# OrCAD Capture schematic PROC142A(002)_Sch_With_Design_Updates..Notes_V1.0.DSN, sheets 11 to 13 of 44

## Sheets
11 10. PERIPHERAL POWER SUPPLY-1: size C; title: PERIPHERAL POWER SUPPLY -1
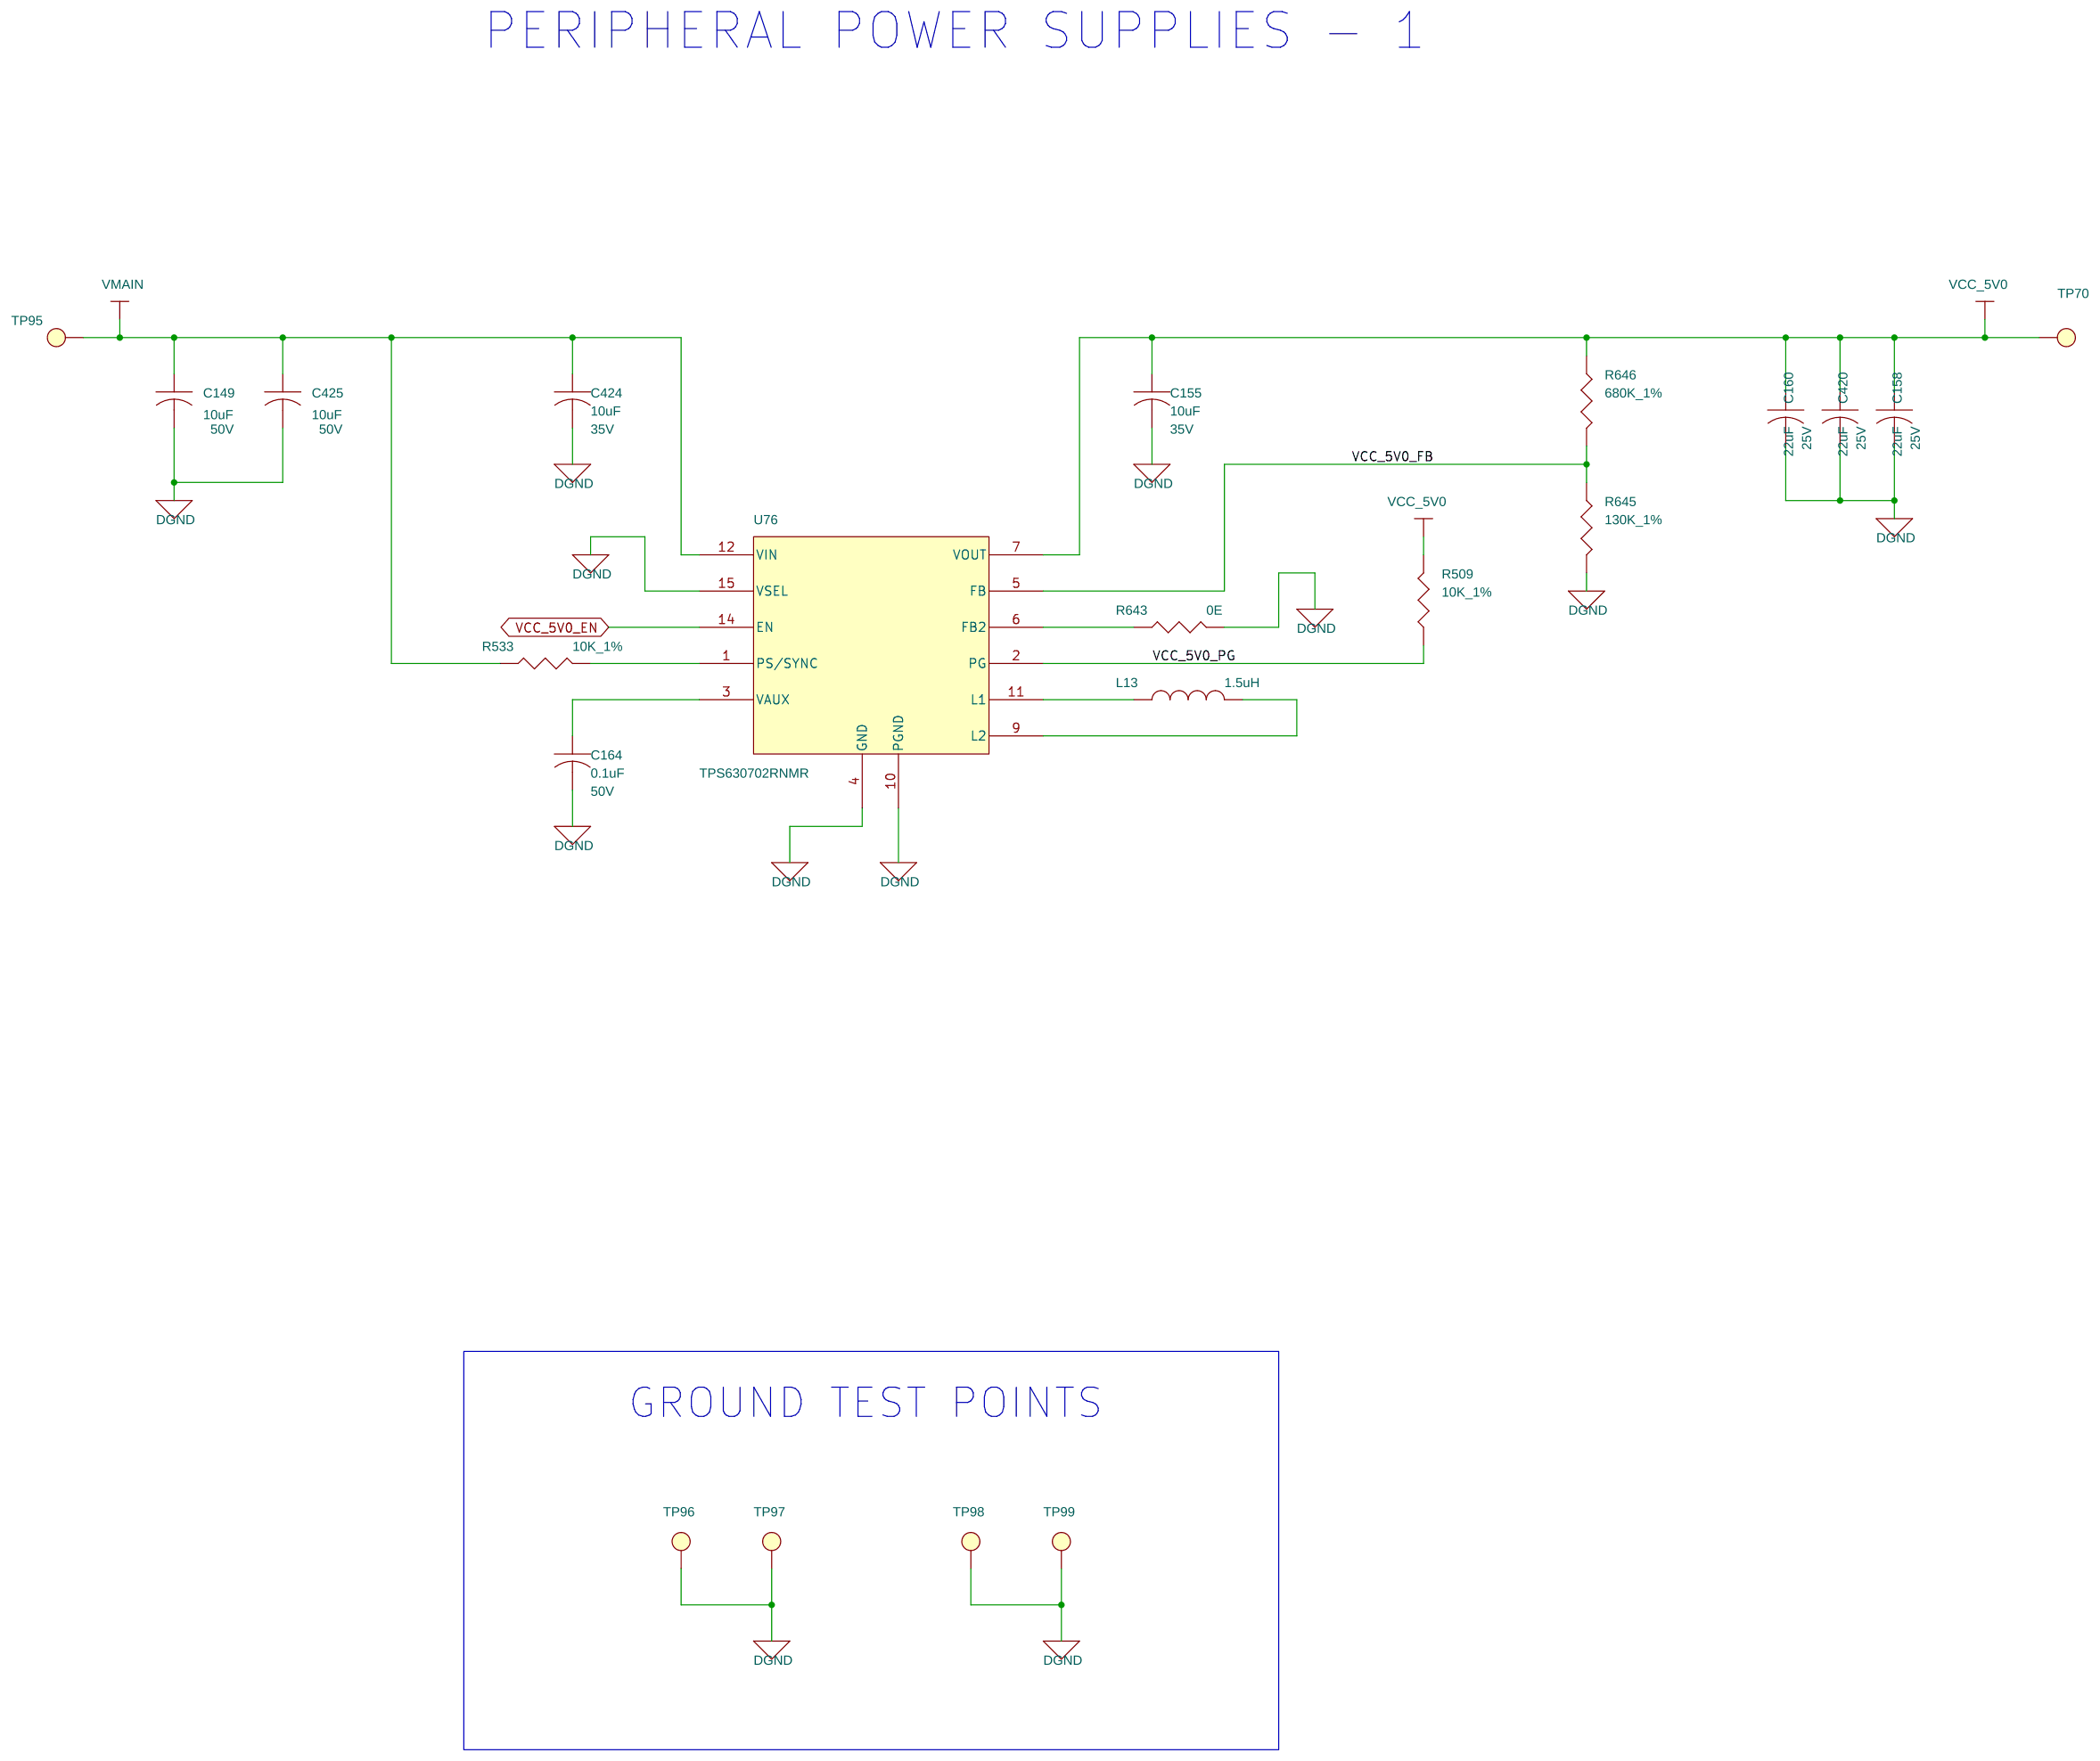
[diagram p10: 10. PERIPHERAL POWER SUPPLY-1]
12 11. PERIPHERAL POWER SUPPLY-2: size C; title: PERIPHERAL POWER SUPPLY-2
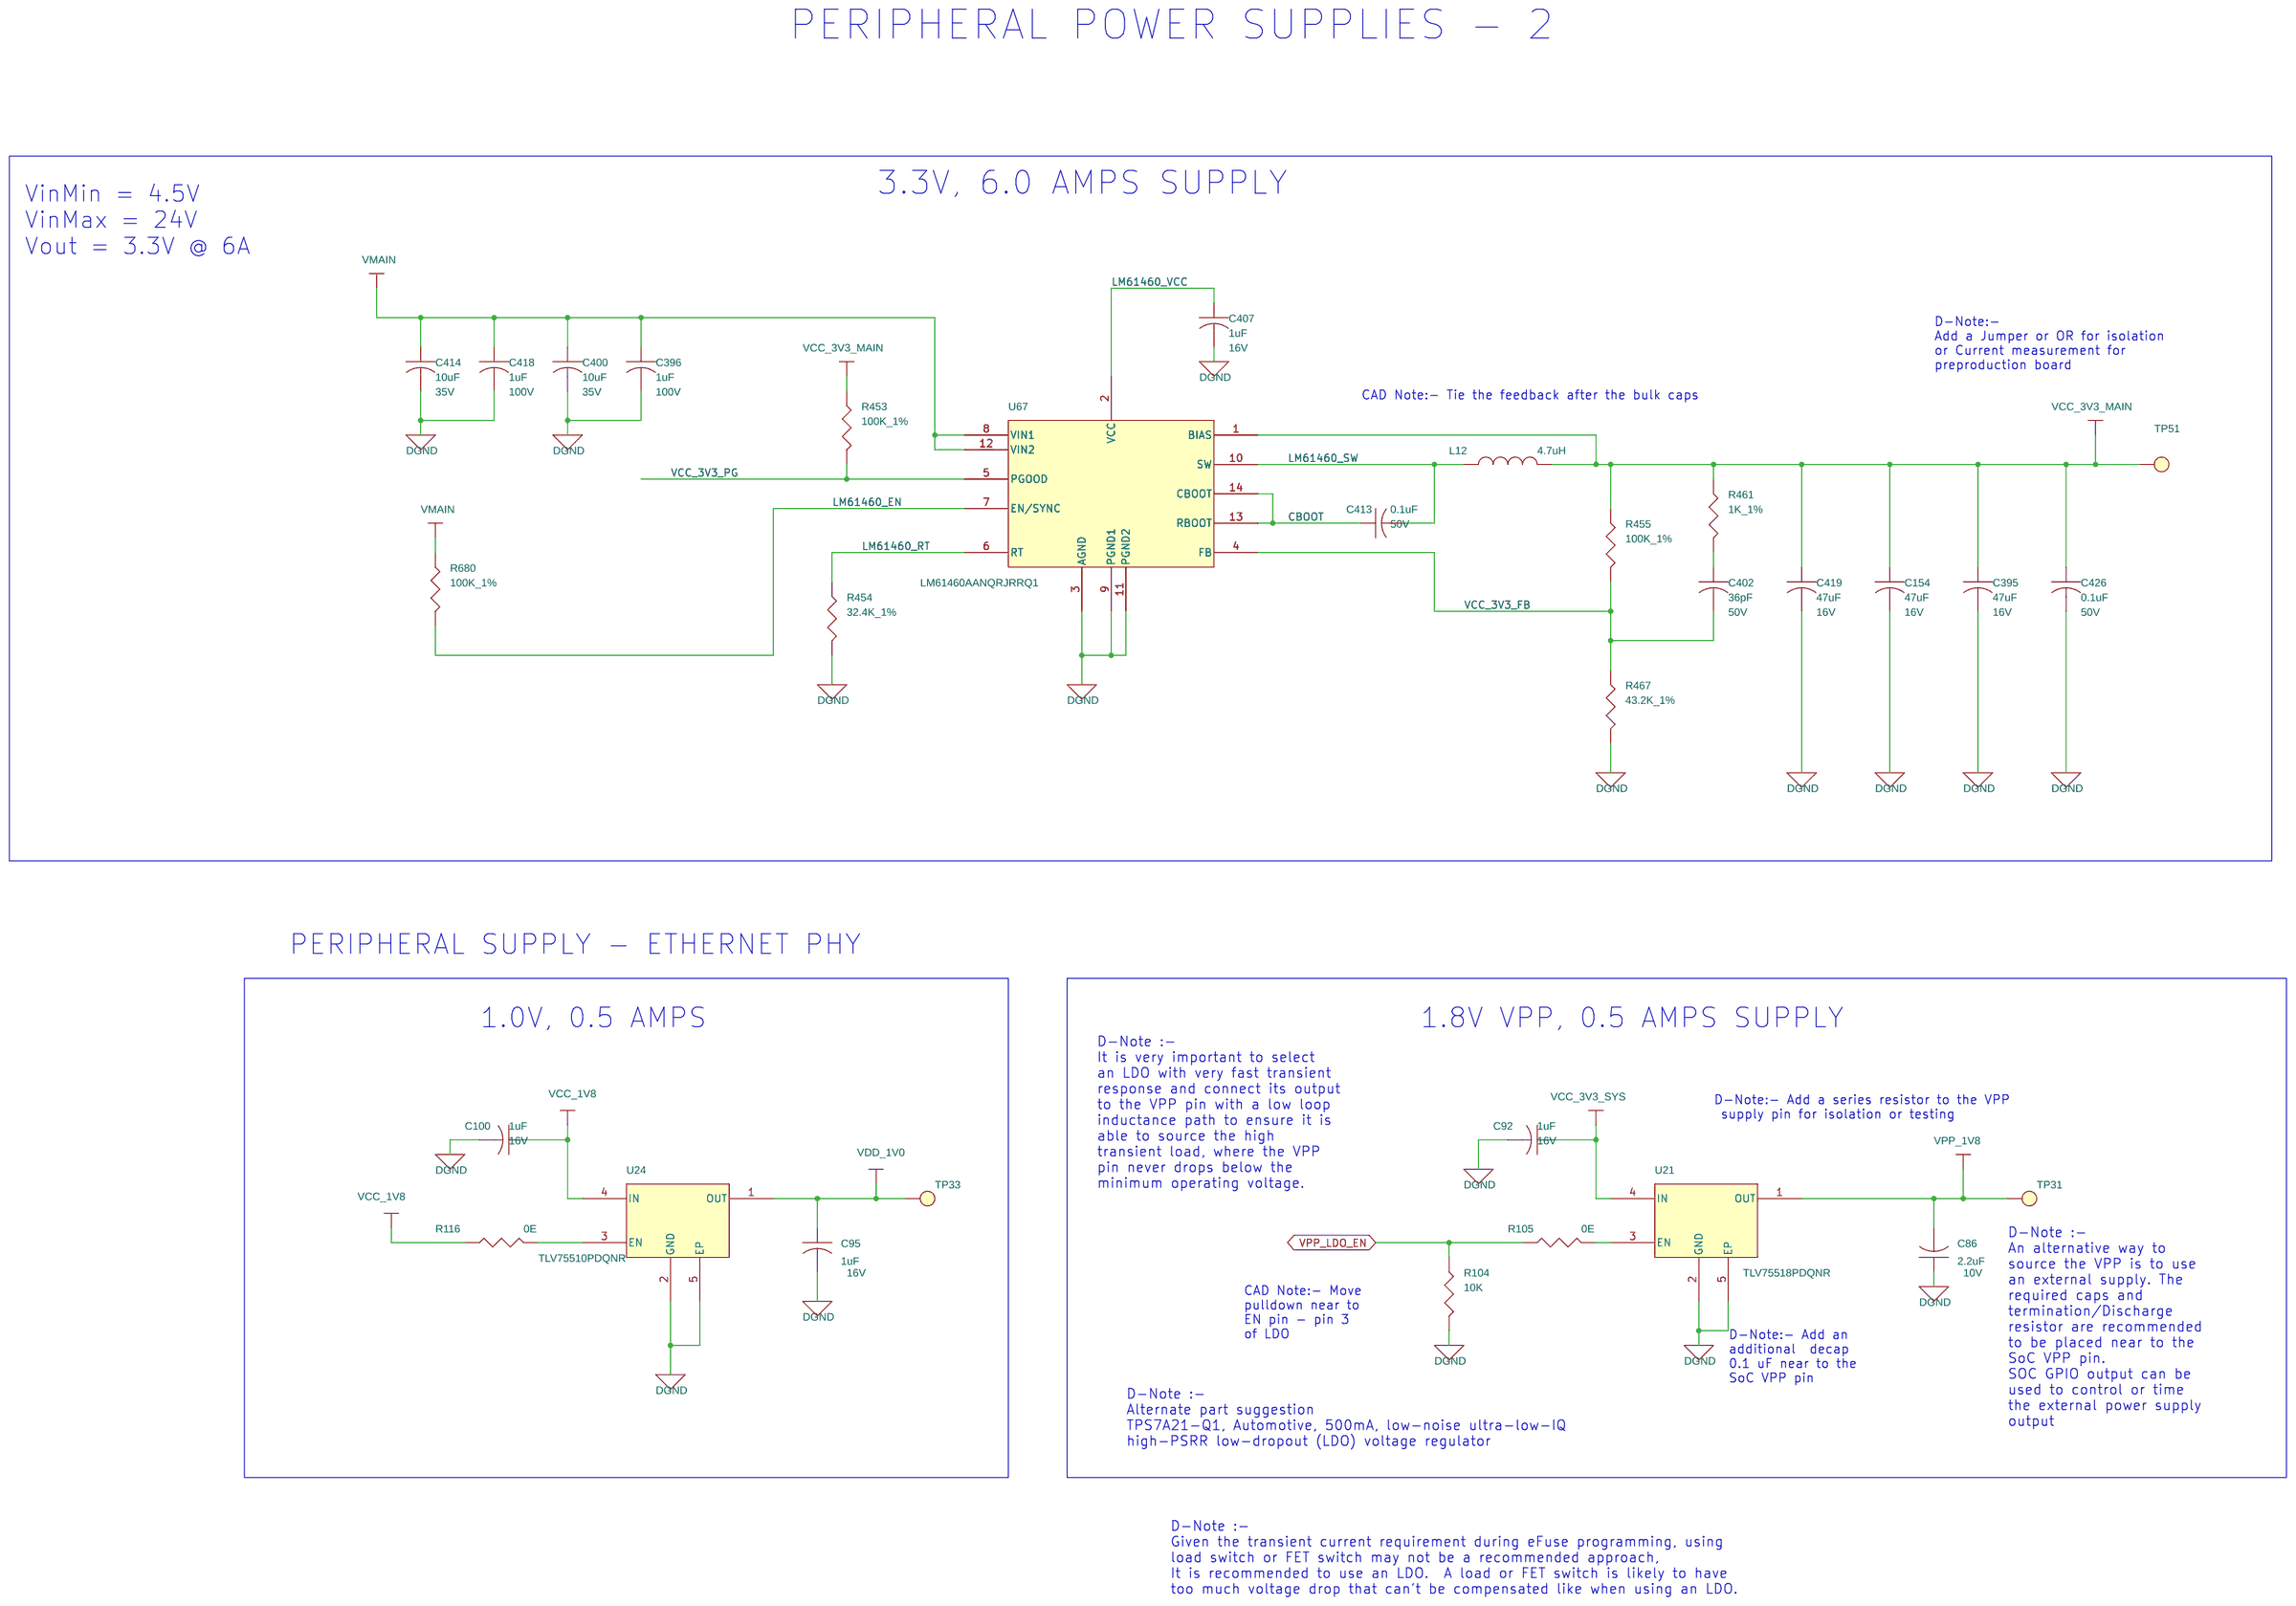
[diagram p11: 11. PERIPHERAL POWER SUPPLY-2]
13 12. FULTON PMIC: size C; title: SOC POWER SUPPLY
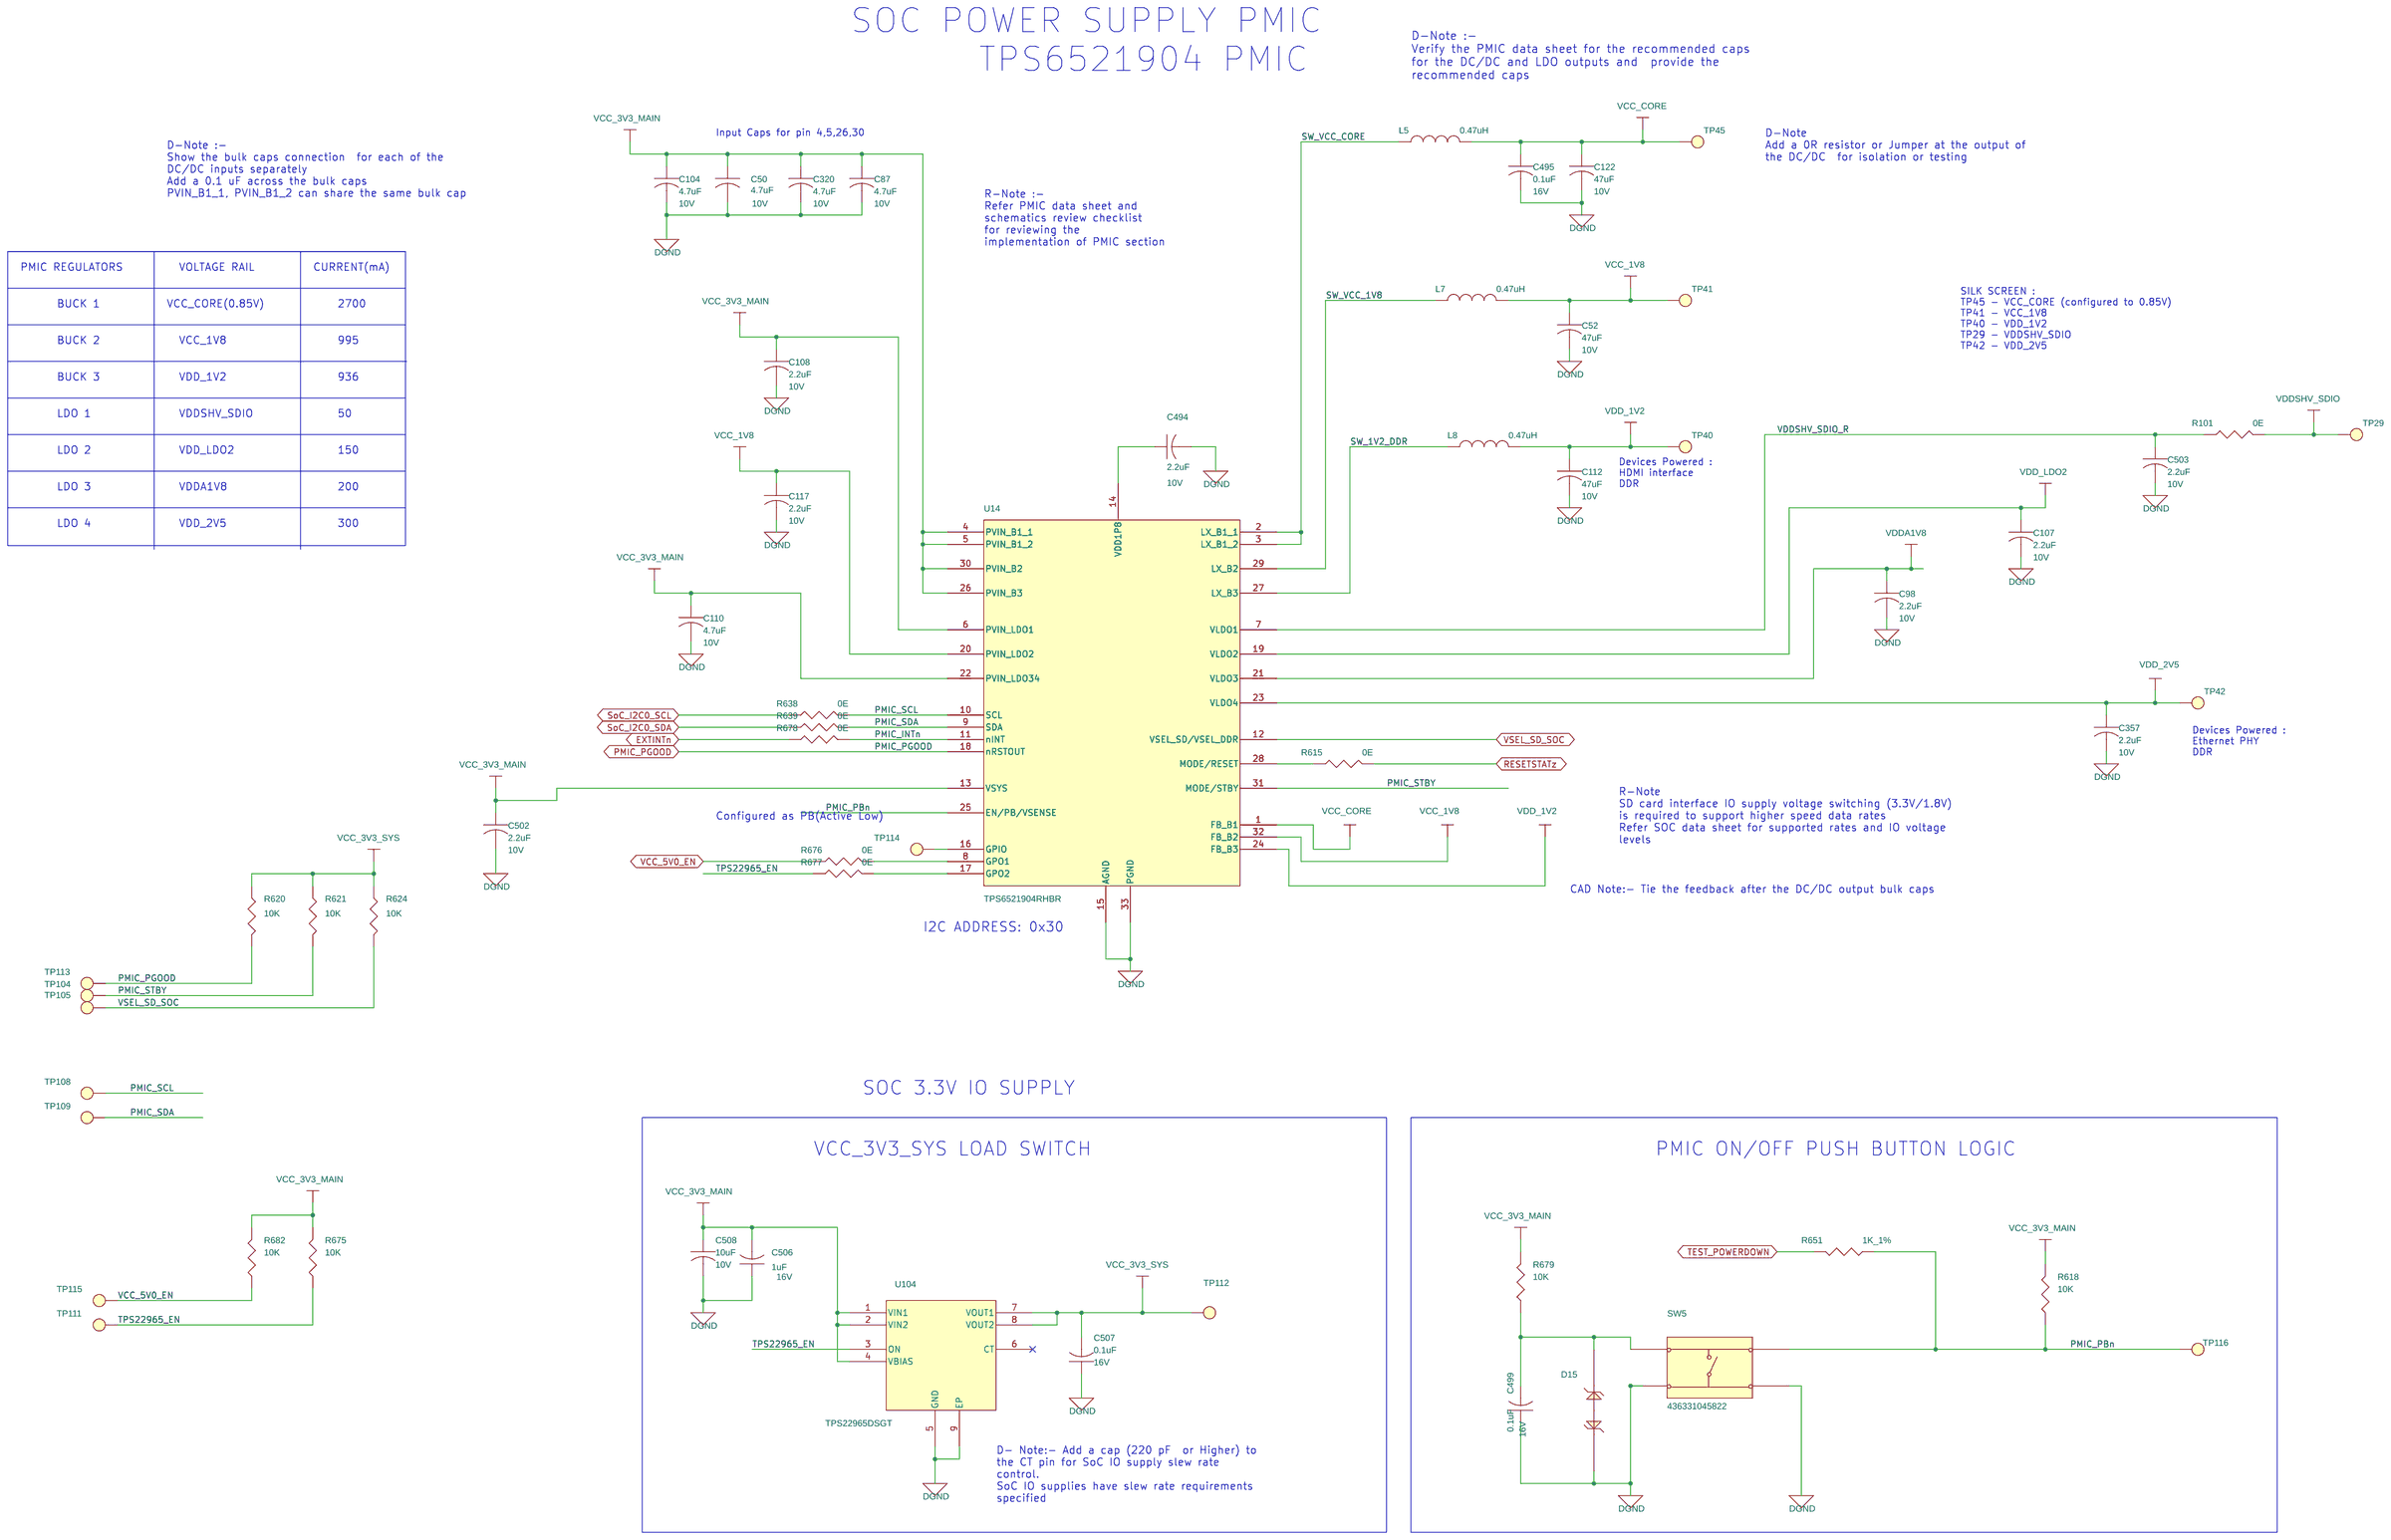
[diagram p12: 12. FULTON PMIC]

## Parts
sheet 10. PERIPHERAL POWER SUPPLY-1
C149  10uF  [CAP0805_1-5]
C155  10uF  [CAP0603_1]
C158  22uF  [CAP0805_1-5]
C160  22uF  [CAP0805_1-5]
C164  0.1uF  [CAP0402_0-75]
C420  22uF  [CAP0805_1-5]
C424  10uF  [CAP0603_1]
C425  10uF  [CAP0805_1-5]
L13  1.5uH  [IND_XFL4020_170X170_SMD_2-1]
R509  10K_1%  [RES0201_0-5]
R533  10K_1%  [RES0201_0-5]
R643  0E  [RES0201_0-5]
R645  130K_1%  [RES0402_0-5]
R646  680K_1%  [RES0402_0-5]
TP70  TP20_SMD  [TP20_SMD]
TP95  TP20_SMD  [TP20_SMD]
TP96  THRU HOLE  [TP_36X22]
TP97  THRU HOLE  [TP_36X22]
TP98  TP20_SMD  [TP20_SMD]
TP99  TP20_SMD  [TP20_SMD]
U76  TPS630702RNMR  [VQFNHR15_TPS630701_100X120_1]
sheet 11. PERIPHERAL POWER SUPPLY-2
C86  2.2uF  [CAP0201_0-5]
C92  1uF  [CAP0201_0-5]
C95  1uF  [CAP0201_0-5]
C100  1uF  [CAP0201_0-5]
C154  47uF  [CAP1210_2-75]
C395  47uF  [CAP1210_2-75]
C396  1uF  [CAP0805_1-5]
C400  10uF  [CAP0603_1]
C402  36pF  [CAP0402_0-75]
C407  1uF  [CAP0201_0-5]
C413  0.1uF  [CAP0402_0-75]
C414  10uF  [CAP0603_1]
C418  1uF  [CAP0805_1-5]
C419  47uF  [CAP1210_2-75]
C426  0.1uF  [CAP0402_0-75]
L12  4.7uH  [IND_XAL6060_260X270_SMD_6-1]
R104  10K  [RES0201_0-5]
R105  0E  [RES0201_0-5]
R116  0E  [RES0201_0-5]
R453  100K_1%  [RES0402_0-5]
R454  32.4K_1%  [RES0402_0-5]
R455  100K_1%  [RES0402_0-5]
R461  1K_1%  [RES0402_0-5]
R467  43.2K_1%  [RES0402_0-5]
R680  100K_1%  [RES0402_0-5]
TP31  TP20_SMD  [TP20_SMD]
TP33  TP20_SMD  [TP20_SMD]
TP51  TP20_SMD  [TP20_SMD]
U21  TLV75518PDQNR  [X2SON4_TLV71318P_40X40_0-4]
U24  TLV75510PDQNR  [X2SON4_TLV71318P_40X40_0-4]
U67  LM61460AANQRJRRQ1  [VQFNHR14_LM61460_160X140_1]
sheet 12. FULTON PMIC
C50  4.7uF  [CAP0402_0-75]
C52  47uF  [CAP0805_1-5]
C87  4.7uF  [CAP0402_0-75]
C98  2.2uF  [CAP0201_0-5]
C104  4.7uF  [CAP0402_0-75]
C107  2.2uF  [CAP0201_0-5]
C108  2.2uF  [CAP0201_0-5]
C110  4.7uF  [CAP0402_0-75]
C112  47uF  [CAP0805_1-5]
C117  2.2uF  [CAP0201_0-5]
C122  47uF  [CAP0805_1-5]
C320  4.7uF  [CAP0402_0-75]
C357  2.2uF  [CAP0201_0-5]
C494  2.2uF  [CAP0201_0-5]
C495  0.1uF  [CAP0201_0-5]
C499  0.1uF  [CAP0201_0-5]
C502  2.2uF  [CAP0201_0-5]
C503  2.2uF  [CAP0201_0-5]
C506  1uF  [CAP0201_0-5]
C507  0.1uF  [CAP0201_0-5]
C508  10uF  [CAP0402_0-75]
D15  TPD1E10B06DPYR  [DIO_DFN0402_0-5]
L5  0.47uH  [IND0806_1-2]
L7  0.47uH  [IND0806_1-2]
L8  0.47uH  [IND0806_1-2]
R101  0E  [RES0402_0-5]
R615  0E  [RES0402_0-5]
R618  10K  [RES0201_0-5]
R620  10K  [RES0201_0-5]
R621  10K  [RES0201_0-5]
R624  10K  [RES0201_0-5]
R638  0E  [RES0201_0-5]
R639  0E  [RES0201_0-5]
R651  1K_1%  [RES0201_0-5]
R675  10K  [RES0201_0-5]
R676  0E  [RES0201_0-5]
R677  0E  [RES0201_0-5]
R678  0E  [RES0201_0-5]
R679  10K  [RES0201_0-5]
R682  10K  [RES0201_0-5]
SW5  436331045822  [SW4_436331045822_190X190_SMD_1-7]
TP29  TP20_SMD  [TP20_SMD]
TP40  TP20_SMD  [TP20_SMD]
TP41  TP20_SMD  [TP20_SMD]
TP42  TP20_SMD  [TP20_SMD]
TP45  TP20_SMD  [TP20_SMD]
TP104  TP20_SMD  [TP20_SMD]
TP105  TP20_SMD  [TP20_SMD]
TP108  TP20_SMD  [TP20_SMD]
TP109  TP20_SMD  [TP20_SMD]
TP111  TP20_SMD  [TP20_SMD]
TP112  TP20_SMD  [TP20_SMD]
TP113  TP20_SMD  [TP20_SMD]
TP114  TP20_SMD  [TP20_SMD]
TP115  TP20_SMD  [TP20_SMD]
TP116  TP20_SMD  [TP20_SMD]
U14  TPS6521904RHBR  [QFN32_19-68_200X200_1_EP3-8]
U104  TPS22965DSGT  [WSON8_19-68_80X80_0-8]

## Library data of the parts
C149 C425 = CAP: CAP CERAMIC 10uF 50V 10% X5R 0805; Chkd/date: MANIRAJA/010321; Crtd /date: ALVY/010321; Custom_Duty: 15%; Customs_HS_Code: 85322990; Distributor_name: DIGIKEY; Distributor_part_number: 490-18663-1-ND; Footprint Path: Y:\MIS_DATABASE\Library\ALTIUM_TOOL\PCB_FOOTPRINTS\Altium_Footprint_Lib.PcbLib; Height: 1.45MM; Library Path: Y:\MIS_DATABASE\Library\ALTIUM_TOOL\SCHEMATICS_PARTS\MS_DISCRETE_Library.schlib; Mfr_name: MURATA; Mfr_part_number: GRM21BR61H106KE43L; Mistral Part No: 120021030002-R; Package: 0805; Part_type: CAPACITORS\CERAMIC; Project: J7ES_SK_BRD; RoHS: RoHS; Temperature: -55°C+85°C; Tolerance: 10%; Voltage: 50V; Wattage: NA; Weight: 6.4mg; Datasheet: Y:\MIS_DATABASE\DATASHEETS\CAPACITORS\GRM21BR61H106KE43.PDF
C155 C400 C414 C424 = CAP: CAP CERAMIC 10uF 35V 20% X5R 0603; Chkd/date: MANIRAJA/170519; Crtd /date: ALVY/160519; Custom_Duty: 15%; Customs_HS_Code: 85322990; Distributor_name: DIGIKEY; Distributor_part_number: 490-13248-1-ND; Footprint Path: Y:\MIS_DATABASE\Library\ALTIUM_TOOL\PCB_FOOTPRINTS\Altium_Footprint_Lib.PcbLib; Height: 1.00MM; Library Path: Y:\MIS_DATABASE\Library\ALTIUM_TOOL\SCHEMATICS_PARTS\MS_DISCRETE_Library.schlib; Mfr_name: MURATA; Mfr_part_number: GRM188R6YA106MA73D; Mistral Part No: 120019050016-R; Package: 0603; Part_type: CAPACITORS\CERAMIC; Project: BRUKER_SD820_COMMONDO; RoHS: RoHS; Temperature: -55°C+85°C; Tolerance: 20%; Voltage: 35V; Wattage: NA; Weight: 9mg; Datasheet: Y:\MIS_DATABASE\DATASHEETS\CAPACITORS\GRM188R6YA106MA73.PDF
C158 C160 C420 = CAP: CAP CERAMIC 22uF 25V 20% X5R 0805; Chkd/date: MANIRAJA/110718; Crtd /date: ALVY/110718; Custom_Duty: 15%; Customs_HS_Code: 85322990; Distributor_name: DIGIKEY; Distributor_part_number: 490-14661-1-ND; Footprint Path: Y:\MIS_DATABASE\Library\ALTIUM_TOOL\PCB_FOOTPRINTS\Altium_Footprint_Lib.PcbLib; Height: 1.45MM; Library Path: Y:\MIS_DATABASE\Library\ALTIUM_TOOL\SCHEMATICS_PARTS\MS_DISCRETE_Library.schlib; Mfr_name: MURATA; Mfr_part_number: GRM21BR61E226ME44K; Mistral Part No: 120013120018-R; Package: 0805; Part_type: CAPACITORS\CERAMIC; Project: TI_J7SVB_PCIE_ADD-ON-CARD; RoHS: RoHS; Temperature: -55°C+85°C; Tolerance: 20%; Voltage: 25V; Wattage: NA; Weight: 9.5mg; Datasheet: Y:\MIS_DATABASE\DATASHEETS\CAPACITORS\GRM21BR61E226ME44K.PDF
C164 C413 C426 = CAP: CAP CERAMIC 0.1uF 50V 10% X7R 0402; Chkd/date: MANIRAJA/261020; Crtd /date: ALVY/211020; Custom_Duty: 15%; Customs_HS_Code: 85322990; Distributor_name: DIGIKEY; Distributor_part_number: 490-10700-1-ND; Footprint Path: Y:\MIS_DATABASE\Library\ALTIUM_TOOL\PCB_FOOTPRINTS\Altium_Footprint_Lib.PcbLib; Height: 0.55MM; Library Path: Y:\MIS_DATABASE\Library\ALTIUM_TOOL\SCHEMATICS_PARTS\MS_DISCRETE_Library.schlib; Mfr_name: MURATA; Mfr_part_number: GRM155R71H104KE14D; Mistral Part No: 120011100014-R; Package: 0402; Part_type: CAPACITORS\CERAMIC; Project: J7_CP; RoHS: RoHS; Temperature: -55°C+125°C; Tolerance: 10%; Voltage: 50V; Wattage: NA; Weight: 3.1mg; Datasheet: Y:\MIS_DATABASE\DATASHEETS\CAPACITORS\GRM155R71H104KE14.PDF
L13 = INDUCTOR: IND POWER 1.5uH 9.1A 20% SMD; Chkd/date: MANIRAJA/101019; Crtd /date: MANIRAJA/101019; Custom_Duty: 24%; Customs_HS_Code: 85437099; Distributor_name: MOUSER; Distributor_part_number: 994-XFL4020-152MEB; Footprint Path: Y:\MIS_DATABASE\Library\ALTIUM_TOOL\PCB_FOOTPRINTS\Altium_Footprint_Lib.PcbLib; Height: 2.10MM; Library Path: Y:\MIS_DATABASE\Library\ALTIUM_TOOL\SCHEMATICS_PARTS\MS_DISCRETE_Library.schlib; Mfr_name: COIL CRAFT; Mfr_part_number: XFL4020-152MEB; Mistral Part No: 130019100011-R; Package: SMD; Project: NPOL_UAIS_CONTROLLER-CARD; RoHS: RoHS; Temperature: -40°C+125°C; Tolerance: 20%; Voltage: NA; Wattage: NA; Weight: 169mg; Datasheet: Y:\MIS_DATABASE\DATASHEETS\DISCRETES\INDUCTORS\XFL4020.PDF
R509 R533 = RESISTOR: RES 10K 1/20W 1% 0201; Chkd/date: VASANTHA/270117; Crtd /date: MANIRAJA/270117; Custom_Duty: 15%; Customs_HS_Code: 85332119; Distributor_name: DIGIKEY; Distributor_part_number: 311-10.0KMCT-ND; Footprint Path: Y:\MIS_DATABASE\Library\ALTIUM_TOOL\PCB_FOOTPRINTS\Altium_Footprint_Lib.PcbLib; Height: 0.26MM; Library Path: Y:\MIS_DATABASE\Library\ALTIUM_TOOL\SCHEMATICS_PARTS\MS_DISCRETE_Library.schlib; Mfr_name: YAGEO AMERICA; Mfr_part_number: RC0201FR-0710KL; Mistral Part No: 110011040018-R; Package: 0201; Part_type: RESISTORS\FIXED; Project: GOLDEN-I LITE; RoHS: RoHS; Temperature: -55°C+125°C; Tolerance: 1%; Voltage: NA; Wattage: 1/20W; Weight: 0.17mg; Datasheet: Y:\MIS_DATABASE\DATASHEETS\RESISTORS\RCXXXXL-SER_MAR18.PDF
R105 R116 R638 R639 R643 R676-R678 = RESISTOR: RES 0E 1/20W 5% 0201; Chkd/date: NAVEED/301214; Crtd /date: MUDDU/120710; Custom_Duty: 15%; Customs_HS_Code: 85332119; Distributor_name: DIGIKEY; Distributor_part_number: 311-0.0NCT-ND; Footprint Path: Y:\MIS_DATABASE\Library\ALTIUM_TOOL\PCB_FOOTPRINTS\Altium_Footprint_Lib.PcbLib; Height: 0.26MM; Library Path: Y:\MIS_DATABASE\Library\ALTIUM_TOOL\SCHEMATICS_PARTS\MS_DISCRETE_Library.schlib; Mfr_name: YAGEO AMERICA; Mfr_part_number: RC0201JR-070RL; Mistral Part No: 110010070067-R; Package: 0201; Part_type: RESISTORS\FIXED; Project: PB_BUGBASE; RoHS: RoHS; Temperature: -55°C+125°C; Tolerance: 5%; Voltage: NA; Wattage: 1/20W; Weight: 0.17mg; Datasheet: Y:\MIS_DATABASE\DATASHEETS\RESISTORS\RCXXXXL-SER_MAR18.PDF
R645 = RESISTOR: RES 130K 1/10W 1% 0402; Chkd/date: MAZHAR/150611; Crtd /date: BAVISH/020611; Custom_Duty: 15%; Customs_HS_Code: 85332119; Distributor_name: DIGIKEY; Distributor_part_number: P130KLCT-ND; Footprint Path: Y:\MIS_DATABASE\Library\ALTIUM_TOOL\PCB_FOOTPRINTS\Altium_Footprint_Lib.PcbLib; Height: 0.40MM; Library Path: Y:\MIS_DATABASE\Library\ALTIUM_TOOL\SCHEMATICS_PARTS\MS_DISCRETE_Library.schlib; Mfr_name: PANASONIC-ECG; Mfr_part_number: ERJ-2RKF1303X; Mistral Part No: 110011060012-R; Package: 0402; Part_type: RESISTORS\FIXED; Project: AM4515_EVM_LCD; RoHS: RoHS; Temperature: -55°C+155°C; Tolerance: 1%; Voltage: NA; Wattage: 1/10W; Weight: 0.8mg; Datasheet: Y:\MIS_DATABASE\DATASHEETS\RESISTORS\PAN-ERJSER_NOV17.PDF
R646 = RESISTOR: RES 680K 1/10W 1% 0402; Chkd/date: SUHAS/200411; Crtd /date: MAZHAR/180411; Custom_Duty: 15%; Customs_HS_Code: 85332119; Distributor_name: DIGIKEY; Distributor_part_number: P680KLCT-ND; Footprint Path: Y:\MIS_DATABASE\Library\ALTIUM_TOOL\PCB_FOOTPRINTS\Altium_Footprint_Lib.PcbLib; Height: 0.40MM; Library Path: Y:\MIS_DATABASE\Library\ALTIUM_TOOL\SCHEMATICS_PARTS\MS_DISCRETE_Library.schlib; Mfr_name: PANASONIC-ECG; Mfr_part_number: ERJ-2RKF6803X; Mistral Part No: 110011040004-R; Package: 0402; Part_type: RESISTORS\FIXED; Project: AM4515_EVM_LCD; RoHS: RoHS; Temperature: -55°C+155°C; Tolerance: 1%; Voltage: NA; Wattage: 1/10W; Weight: 0.8mg; Datasheet: Y:\MIS_DATABASE\DATASHEETS\RESISTORS\PAN-ERJSER_NOV17.PDF
TP29 TP31 TP33 TP40-TP42 TP45 TP51 TP70 TP95 TP98 TP99 TP104 TP105 TP108 TP109 TP111-TP116 = TESTPOINT: TESTPOINT CIR 20 SMD; Chkd/date: SHREESHAIL/171006; Crtd /date: MAZHAR/171006; Custom_Duty: NA; Customs_HS_Code: NA; Distributor_name: NA; Distributor_part_number: NA; Footprint Path: Y:\MIS_DATABASE\Library\ALTIUM_TOOL\PCB_FOOTPRINTS\Altium_Footprint_Lib.PcbLib; Height: NA; Library Path: Y:\MIS_DATABASE\Library\ALTIUM_TOOL\SCHEMATICS_PARTS\MS_DISCRETE_Library.schlib; MECHANICAL 3D STEP FILE: NA; Mfr_name: LOCAL; Mistral Part No: NA; Package: SMD; Project: BT MODULE_CSRBC04; RoHS: NA; Temperature: NA; Tolerance: NA; Voltage: NA; Wattage: NA; Weight: NA; Datasheet: NA
TP96 TP97 = TESTPOINT: TESTPOINT 0.56MM DRILL PTH; Chkd/date: BAVISH/040311; Crtd /date: MAZHAR/110405; Distributor_name: NA; Distributor_part_number: NA; Height: NA; Mfr_name: LOCAL; Mistral Part No: 130010010008; Package: THRU-HOLE; Project: KOPIN_MODULS; Temperature: NA; Tolerance: NA; Voltage: NA; Wattage: NA; Weight: NA; Datasheet: NA
U76 = TPS630701_VQFN-HR15: IC ADJ BUCK-BOOST CONVERTER WITH 3.6A SWITCH CURRENT VQFN-HR15; Chkd/date: ALVY/250122; Crtd /date: MANIRAJA/250122; Custom_Duty: 15%; Customs_HS_Code: 85423100; Distributor_name: DIGIKEY; Distributor_part_number: 296-TPS630702RNMRCT-ND; Footprint Path: Y:\MIS_DATABASE\Library\ALTIUM_TOOL\PCB_FOOTPRINTS\Altium_Footprint_Lib.PcbLib; Height: 1.00MM; Library Path: Y:\MIS_DATABASE\Library\ALTIUM_TOOL\SCHEMATICS_PARTS\MS_MISCPOWER_Library.schlib; Mfr_name: TEXAS INSTRUMENTS; Mistral Part No: 142022010015-R; Package: VQFN-HR15; Part_type: ICS\POWER\DC-DC CONVERTER; Project: AM62X_SKEVM; RoHS: RoHS; Temperature: -40°C+125°C; Tolerance: NA; Voltage: NA; Wattage: NA; Weight: 17.7mg; Datasheet: Y:\MIS_DATABASE\DATASHEETS\ICS\POWER\TPS630701X.PDF
C86 C494 C502 = CAP: CAP CERAMIC 2.2uF 10V 10% X5R 0201; Chkd/date: MANIRAJA/220918; Crtd /date: MANIRAJA/220918; Custom_Duty: 15%; Customs_HS_Code: 85322990; Distributor_name: DIGIKEY; Distributor_part_number: 490-13227-1-ND; Footprint Path: Y:\MIS_DATABASE\Library\ALTIUM_TOOL\PCB_FOOTPRINTS\Altium_Footprint_Lib.PcbLib; Height: 0.39MM; Library Path: Y:\MIS_DATABASE\Library\ALTIUM_TOOL\SCHEMATICS_PARTS\MS_DISCRETE_Library.schlib; Mfr_name: MURATA; Mfr_part_number: GRM033R61A225KE47D; Mistral Part No: 120018090044-R; Package: 0201; Part_type: CAPACITORS\CERAMIC; Project: TI_60GHz-AOP; RoHS: RoHS; Temperature: -55°C+85°C; Tolerance: 10%; Voltage: 10V; Wattage: NA; Weight: 0.33mg; Datasheet: Y:\MIS_DATABASE\DATASHEETS\CAPACITORS\GRM033R61A225KE47D.PDF
C92 C95 C100 C407 C506 = CAP: CAP CERAMIC 1uF 16V 20% X5R 0201; Chkd/date: MANIRAJA/300520; Crtd /date: ALVY/260520; Custom_Duty: 15%; Customs_HS_Code: 85322990; Distributor_name: DIGIKEY; Distributor_part_number: 490-18654-1-ND; Footprint Path: Y:\MIS_DATABASE\Library\ALTIUM_TOOL\PCB_FOOTPRINTS\Altium_Footprint_Lib.PcbLib; Height: 0.39MM; Library Path: Y:\MIS_DATABASE\Library\ALTIUM_TOOL\SCHEMATICS_PARTS\MS_DISCRETE_Library.schlib; Mfr_name: MURATA; Mfr_part_number: GRM033R61C105ME15D; Mistral Part No: 120018090038-R; Package: 0201; Part_type: CAPACITORS\CERAMIC; Project: QCS610_NANOSOM; RoHS: RoHS; Temperature: -55°C+85°C; Tolerance: 20%; Voltage: 16V; Wattage: NA; Weight: 0.33mg; Datasheet: Y:\MIS_DATABASE\DATASHEETS\CAPACITORS\GRM033R61C105ME15.PDF
C154 C395 C419 = CAP: CAP CERAMIC 47uF 16V 10% X6S 1210; Chkd/date: ALVY/010721; Crtd /date: MANIRAJA/010721; Custom_Duty: 15%; Customs_HS_Code: 85322990; Distributor_name: DIGIKEY; Distributor_part_number: 490-10531-1-ND; Footprint Path: Y:\MIS_DATABASE\Library\ALTIUM_TOOL\PCB_FOOTPRINTS\Altium_Footprint_Lib.PcbLib; Height: 2.70MM; Library Path: Y:\MIS_DATABASE\Library\ALTIUM_TOOL\SCHEMATICS_PARTS\MS_DISCRETE_Library.schlib; Mfr_name: MURATA; Mfr_part_number: GRM32EC81C476KE15L; Mistral Part No: 120021070001-R; Package: 1210; Part_type: CAPACITORS\CERAMIC; Project: TI_AM263X_CC; RoHS: RoHS; Temperature: -55°C+105°C; Tolerance: 10%; Voltage: 16V; Wattage: NA; Weight: 100mg; Datasheet: Y:\MIS_DATABASE\DATASHEETS\CAPACITORS\GRM32EC81C476KE15.PDF
C396 C418 = CAP: CAP CERAMIC 1uF 100V 10% X7S 0805; Chkd/date: MANIRAJA/160921; Crtd /date: ALVY/150921; Custom_Duty: 15%; Customs_HS_Code: 85322990; Distributor_name: DIGIKEY; Distributor_part_number: 490-14464-1-ND; Footprint Path: Y:\MIS_DATABASE\Library\ALTIUM_TOOL\PCB_FOOTPRINTS\Altium_Footprint_Lib.PcbLib; Height: 1.45MM; Library Path: Y:\MIS_DATABASE\Library\ALTIUM_TOOL\SCHEMATICS_PARTS\MS_DISCRETE_Library.schlib; Mfr_name: MURATA; Mfr_part_number: GRM21BC72A105KE01L; Mistral Part No: 120013030002-R; Package: 0805; Part_type: CAPACITORS\CERAMIC; Project: TI_AM62x SKEVM_BRD; RoHS: RoHS; Temperature: -55°C+125°C; Tolerance: 10%; Voltage: 100V; Wattage: NA; Weight: 6.4mg; Datasheet: Y:\MIS_DATABASE\DATASHEETS\CAPACITORS\GRM21BC72A105KE01.PDF
C402 = CAP: CAP CERAMIC 36pF 50V 2% HI-Q C0G(NP0) 0402; Chkd/date: MANIRAJA/061021; Crtd /date: ALVY/051021; Custom_Duty: 15%; Customs_HS_Code: 85322990; Distributor_name: DIGIKEY; Distributor_part_number: 490-GJM1555C1H360GB01DTR-ND; Footprint Path: Y:\MIS_DATABASE\Library\ALTIUM_TOOL\PCB_FOOTPRINTS\Altium_Footprint_Lib.PcbLib; Height: 0.55MM; Library Path: Y:\MIS_DATABASE\Library\ALTIUM_TOOL\SCHEMATICS_PARTS\MS_DISCRETE_Library.schlib; Mfr_name: MURATA; Mfr_part_number: GJM1555C1H360GB01D; Mistral Part No: 120021100002-R; Package: 0402; Part_type: CAPACITORS\CERAMIC; Project: TI_AM62x SKEVM_BRD; RoHS: RoHS; Temperature: -55°C+125°C; Tolerance: 2%; Voltage: 50V; Wattage: NA; Weight: 1.5mg; Datasheet: Y:\MIS_DATABASE\DATASHEETS\CAPACITORS\GJM1555C1H360GB01.PDF
L12 = INDUCTOR: IND POWER 4.7uH 11A 20% SMD; Chkd/date: VASANTHA/090317; Crtd /date: MANIRAJA/090317; Custom_Duty: 15%; Customs_HS_Code: 85412900; Distributor_name: MOUSER; Distributor_part_number: 994-XAL6060-472MEB; Footprint Path: Y:\MIS_DATABASE\Library\ALTIUM_TOOL\PCB_FOOTPRINTS\Altium_Footprint_Lib.PcbLib; Height: 6.10MM; Library Path: Y:\MIS_DATABASE\Library\ALTIUM_TOOL\SCHEMATICS_PARTS\MS_DISCRETE_Library.schlib; Mfr_name: COILCRAFT; Mfr_part_number: XAL6060-472MEB; Mistral Part No: 130015090013-R; Package: SMD; Project: OCTBTS_3000; RoHS: RoHS; Temperature: -40°C+125°C; Tolerance: 20%; Voltage: NA; Wattage: NA; Weight: 1600g; Datasheet: Y:\MIS_DATABASE\DATASHEETS\DISCRETES\INDUCTORS\XAL6060-SER.PDF
R104 = RESISTOR: RES 10K 1/20W 5% 0201; Chkd/date: MANIRAJA/050517; Crtd /date: MANIRAJA/050517; Custom_Duty: 15%; Customs_HS_Code: 85332119; Distributor_name: DIGIKEY; Distributor_part_number: 311-10KNCT-ND; Footprint Path: Y:\MIS_DATABASE\Library\ALTIUM_TOOL\PCB_FOOTPRINTS\Altium_Footprint_Lib.PcbLib; Height: 0.26MM; Library Path: Y:\MIS_DATABASE\Library\ALTIUM_TOOL\SCHEMATICS_PARTS\MS_DISCRETE_Library.schlib; Mfr_name: YAGEO AMERICA; Mfr_part_number: RC0201JR-0710KL; Mistral Part No: 110010070051-R; Package: 0201; Part_type: RESISTORS\FIXED; Project: GOLDEN-I LITE; RoHS: RoHS; Temperature: -55°C+125°C; Tolerance: 5%; Voltage: NA; Wattage: 1/20W; Weight: 0.17mg; Datasheet: Y:\MIS_DATABASE\DATASHEETS\RESISTORS\RCXXXXL-SER_MAR18.PDF
R453 R455 R680 = RESISTOR: RES 100K 1/10W 1% 0402; Chkd/date: VASANTHA/201216; Crtd /date: MAZHAR/130306; Custom_Duty: 15%; Customs_HS_Code: 85332119; Distributor_name: DIGIKEY; Distributor_part_number: P100KLCT-ND; Footprint Path: Y:\MIS_DATABASE\Library\ALTIUM_TOOL\PCB_FOOTPRINTS\Altium_Footprint_Lib.PcbLib; Height: 0.40MM; Library Path: Y:\MIS_DATABASE\Library\ALTIUM_TOOL\SCHEMATICS_PARTS\MS_DISCRETE_Library.schlib; Mfr_name: PANASONIC-ECG; Mfr_part_number: ERJ-2RKF1003X; Mistral Part No: 110009030187-R; Package: 0402; Part_type: RESISTORS\FIXED; Project: J32; RoHS: RoHS; Temperature: -55°C+155°C; Tolerance: 1%; Voltage: NA; Wattage: 1/10W; Weight: 0.8mg; Datasheet: Y:\MIS_DATABASE\DATASHEETS\RESISTORS\PAN-ERJSER_NOV17.PDF
R454 = RESISTOR: RES 32.4K 1/16W 1% 0402; Chkd/date: MANIRAJA/080420; Crtd /date: ALVY/080420; Custom_Duty: 15%; Customs_HS_Code: 85332119; Distributor_name: DIGIKEY; Distributor_part_number: 541-32.4KLCT-ND; Footprint Path: Y:\MIS_DATABASE\Library\ALTIUM_TOOL\PCB_FOOTPRINTS\Altium_Footprint_Lib.PcbLib; Height: 0.40MM; Library Path: Y:\MIS_DATABASE\Library\ALTIUM_TOOL\SCHEMATICS_PARTS\MS_DISCRETE_Library.schlib; Mfr_name: VISHAY; Mfr_part_number: CRCW040232K4FKED; Mistral Part No: 110020040003-R; Package: 0402; Part_type: RESISTORS\FIXED; Project: HSDTRS_FEE_BRD; RoHS: RoHS; Temperature: -55°C+155°C; Tolerance: 1%; Voltage: NA; Wattage: 1/16W; Weight: 0.65mg; Datasheet: Y:\MIS_DATABASE\DATASHEETS\RESISTORS\CRCW0603.PDF
R461 = RESISTOR: RES 1K 1/10W 1% 0402; Chkd/date: VASANTHA/281216; Crtd /date: MAZHAR/150506; Custom_Duty: 15%; Customs_HS_Code: 85332119; Distributor_name: DIGIKEY; Distributor_part_number: P1.00KLCT-ND; Footprint Path: Y:\MIS_DATABASE\Library\ALTIUM_TOOL\PCB_FOOTPRINTS\Altium_Footprint_Lib.PcbLib; Height: 0.40MM; Library Path: Y:\MIS_DATABASE\Library\ALTIUM_TOOL\SCHEMATICS_PARTS\MS_DISCRETE_Library.schlib; Mfr_name: PANASONIC-ECG; Mfr_part_number: ERJ-2RKF1001X; Mistral Part No: 110009030411-R; Package: 0402; Part_type: RESISTORS\FIXED; Project: VOCERA; RoHS: RoHS; Temperature: -55°C+155°C; Tolerance: 1%; Voltage: NA; Wattage: 1/10W; Weight: 0.8mg; Datasheet: Y:\MIS_DATABASE\DATASHEETS\RESISTORS\PAN-ERJSER_NOV17.PDF
R467 = RESISTOR: RES 43.2K 1/16W 1% 0402; Chkd/date: MANIRAJA/250821; Crtd /date: ALVY/250821; Custom_Duty: 15%; Customs_HS_Code: 85332119; Distributor_name: DIGIKEY; Distributor_part_number: 541-43.2KLCT-ND; Footprint Path: Y:\MIS_DATABASE\Library\ALTIUM_TOOL\PCB_FOOTPRINTS\Altium_Footprint_Lib.PcbLib; Height: 0.40MM; Library Path: Y:\MIS_DATABASE\Library\ALTIUM_TOOL\SCHEMATICS_PARTS\MS_DISCRETE_Library.schlib; Mfr_name: VISHAY; Mfr_part_number: CRCW040243K2FKED; Mistral Part No: 110021080019-R; Package: 0402; Part_type: RESISTORS\FIXED; Project: TI_AM62x SKEVM_BRD; RoHS: RoHS; Temperature: -55°C+155°C; Tolerance: 1%; Voltage: NA; Wattage: 1/16W; Weight: 0.65mg; Datasheet: Y:\MIS_DATABASE\DATASHEETS\RESISTORS\CRCW0603.PDF
U21 = TLV71318PDQNR_X2SON4: IC 500mA LOW IQ LDO REGULATOR X2SON-4; Crtd /date: ALVY/160620; Custom_Duty: 15%; Customs_HS_Code: 85423100; Distributor_name: DIGIKEY; Distributor_part_number: 296-51790-1-ND; Footprint Path: Y:\MIS_DATABASE\Library\ALTIUM_TOOL\PCB_FOOTPRINTS\Altium_Footprint_Lib.PcbLib; Height: 0.40MM; Library Path: Y:\MIS_DATABASE\Library\ALTIUM_TOOL\SCHEMATICS_PARTS\MS_MISCPOWER_Library.schlib; Mfr_name: TEXAS INSTRUMENTS; Mistral Part No: 142020060013-R; Package: X2SON-4; Part_type: ICS\POWER\VOLTAGE REGULATOR; Project: AM64x-GP_EVM BRD; RoHS: RoHS; Temperature: -40°C+125°C; Tolerance: NA; Voltage: NA; Wattage: NA; Weight: 1.1mg; Datasheet: Y:\MIS_DATABASE\DATASHEETS\ICS\POWER\TLV755P.PDF
U24 = TLV71318PDQNR_X2SON4: IC 500mA 1V LOW IQ LDO REGULATOR X2SON-4; Chkd/date: MANIRAJA/240821; Crtd /date: ALVY/240821; Custom_Duty: 15%; Customs_HS_Code: 85423100; Distributor_name: DIGIKEY; Distributor_part_number: 296-51782-1-ND; Footprint Path: Y:\MIS_DATABASE\Library\ALTIUM_TOOL\PCB_FOOTPRINTS\Altium_Footprint_Lib.PcbLib; Height: 0.40MM; Library Path: Y:\MIS_DATABASE\Library\ALTIUM_TOOL\SCHEMATICS_PARTS\MS_MISCPOWER_Library.schlib; Mfr_name: TEXAS INSTRUMENTS; Mistral Part No: 142021080018-R; Package: X2SON-4; Part_type: ICS\POWER\VOLTAGE REGULATOR; Project: TI_AM62x SKEVM_BRD; RoHS: RoHS; Temperature: -40°C+125°C; Tolerance: NA; Voltage: NA; Wattage: NA; Weight: 1.1mg; Datasheet: Y:\MIS_DATABASE\DATASHEETS\ICS\POWER\TLV755P.PDF
U67 = LM61460_VQFNHR14: IC 6A ADJ AUTO LOW EMI SYNCHRONOUS STEP DOWN DC-DC CONVERTER VQFN-HR14; Chkd/date: ALVY/040221; Crtd /date: MANIRAJA/030221; Custom_Duty: 15%; Customs_HS_Code: 85423100; Distributor_name: DIGIKEY; Distributor_part_number: 296-LM61460AANQRJRRQ1TR-ND; Footprint Path: Y:\MIS_DATABASE\Library\ALTIUM_TOOL\PCB_FOOTPRINTS\Altium_Footprint_Lib.PcbLib; Height: 1.00MM; Library Path: Y:\MIS_DATABASE\Library\ALTIUM_TOOL\SCHEMATICS_PARTS\MS_MISCPOWER_Library.schlib; Mfr_name: TEXAS INSTRUMENTS; Mistral Part No: 142021020006-R; Package: VQFN-HR14; Part_type: ICS\POWER\DC-DC CONVERTER; Project: J7ES_SK_BRD; RoHS: RoHS; Temperature: -40°C+150°C; Tolerance: NA; Voltage: NA; Wattage: NA; Weight: NA; Datasheet: Y:\MIS_DATABASE\DATASHEETS\ICS\POWER\LM61460-Q1.PDF
C50 C87 C104 C110 C320 = CAP: CAP CERAMIC 4.7uF 10V 20% X5R 0402; Chkd/date: MANIRAJA/110718; Crtd /date: ALVY/110718; Custom_Duty: 15%; Customs_HS_Code: 85322990; Distributor_name: DIGIKEY; Distributor_part_number: 490-14306-1-ND; Footprint Path: Y:\MIS_DATABASE\Library\ALTIUM_TOOL\PCB_FOOTPRINTS\Altium_Footprint_Lib.PcbLib; Height: 0.65MM; Library Path: Y:\MIS_DATABASE\Library\ALTIUM_TOOL\SCHEMATICS_PARTS\MS_DISCRETE_Library.schlib; Mfr_name: MURATA; Mfr_part_number: GRM155R61A475MEAAD; Mistral Part No: 120012060002-R; Package: 0402; Part_type: CAPACITORS\CERAMIC; Project: TI_J7SVB_PCIE_ADD-ON-CARD; RoHS: RoHS; Temperature: -55°C+85°C; Tolerance: 20%; Voltage: 10V; Wattage: NA; Weight: 14mg; Datasheet: Y:\MIS_DATABASE\DATASHEETS\CAPACITORS\GRM155R61A475MEAAD.PDF
C52 C112 C122 = CAP: CAP CERAMIC 47uF 10V 20% X5R 0805; Chkd/date: MANIRAJA/181018; Crtd /date: ALVY/181018; Custom_Duty: 15%; Customs_HS_Code: 85322990; Distributor_name: DIGIKEY; Distributor_part_number: 490-9961-1-ND; Footprint Path: Y:\MIS_DATABASE\Library\ALTIUM_TOOL\PCB_FOOTPRINTS\Altium_Footprint_Lib.PcbLib; Height: 1.45MM; Library Path: Y:\MIS_DATABASE\Library\ALTIUM_TOOL\SCHEMATICS_PARTS\MS_DISCRETE_Library.schlib; Manufacturer: MURATA; Mfr_name: MURATA; Mfr_part_number: GRM21BR61A476ME15L; Mistral Part No: 120014100011-R; Package: 0805; Part_type: CAPACITORS\CERAMIC; Project: RFID_MODULE-DESIGN; RoHS: RoHS; Temperature: -55°C+85°C; Tolerance: 20%; Voltage: 10V; Wattage: NA; Weight: 9.5mg; Datasheet: Y:\MIS_DATABASE\DATASHEETS\CAPACITORS\GRM21BR61A476ME15L.PDF
C98 C107 C108 C117 C357 C503 = CAP: CAP CERAMIC 2.2uF 10V 10% X5R 0201; Chkd/date: MANIRAJA/220918; Crtd /date: MANIRAJA/220918; Custom_Duty: 15%; Customs_HS_Code: 85322990; Distributor_name: DIGIKEY; Distributor_part_number: 490-13227-1-ND; Footprint Path: Y:\MIS_DATABASE\Library\ALTIUM_TOOL\PCB_FOOTPRINTS\Altium_Footprint_Lib.PcbLib; Height: 0.39MM; Library Path: Y:\MIS_DATABASE\Library\ALTIUM_TOOL\SCHEMATICS_PARTS\MS_DISCRETE_Library.schlib; Manufacturer: MURATA; Mfr_name: MURATA; Mfr_part_number: GRM033R61A225KE47D; Mistral Part No: 120018090044-R; Package: 0201; Part_type: CAPACITORS\CERAMIC; Project: TI_60GHz-AOP; RoHS: RoHS; Temperature: -55°C+85°C; Tolerance: 10%; Voltage: 10V; Wattage: NA; Weight: 0.33mg; Datasheet: Y:\MIS_DATABASE\DATASHEETS\CAPACITORS\GRM033R61A225KE47D.PDF
C495 = CAP: CAP CERAMIC 0.1uF 16V 10% X5R 0201; Chkd/date: MANIRAJA/230118; Crtd /date: MANIRAJA/230118; Custom_Duty: 15%; Customs_HS_Code: 85322990; Distributor_name: DIGIKEY; Distributor_part_number: 490-14305-1-ND; Footprint Path: Y:\MIS_DATABASE\Library\ALTIUM_TOOL\PCB_FOOTPRINTS\Altium_Footprint_Lib.PcbLib; Height: 0.33MM; Library Path: Y:\MIS_DATABASE\Library\ALTIUM_TOOL\SCHEMATICS_PARTS\MS_DISCRETE_Library.schlib; Mfr_name: MURATA; Mfr_part_number: GRM033R61C104KE14D; Mistral Part No: 120009030072-R; Package: 0201; Part_type: CAPACITORS\CERAMIC; Project: TI_MAXIE_CPB; RoHS: RoHS; Temperature: -55°C+85°C; Tolerance: 10%; Voltage: 16V; Wattage: NA; Weight: 0.33mg; Datasheet: Y:\MIS_DATABASE\DATASHEETS\CAPACITORS\GRM033R61C104KE14.PDF
C499 C507 = CAP: CAP CERAMIC 0.1uF 16V 10% X5R 0201; Alt_Mfr_name: YAGEO AMERICA; Alt_Mfr_part_number: CC0402KRX5R8BB104; Chkd/date: MANIRAJA/230118; Crtd /date: MANIRAJA/230118; Custom_Duty: 15%; Customs_HS_Code: 85322990; Distributor_name: DIGIKEY; Distributor_part_number: 490-14305-1-ND; Footprint Path: Y:\MIS_DATABASE\Library\ALTIUM_TOOL\PCB_FOOTPRINTS\Altium_Footprint_Lib.PcbLib; Height: 0.33MM; Library Path: Y:\MIS_DATABASE\Library\ALTIUM_TOOL\SCHEMATICS_PARTS\MS_DISCRETE_Library.schlib; Mfr_name: MURATA; Mfr_part_number: GRM033R61C104KE14D; Mistral Part No: 120009030072-R; Package: 0201; Part_type: CAPACITORS\CERAMIC; Project: TI_MAXIE_CPB; RoHS: RoHS; Temperature: -55°C+85°C; Tolerance: 10%; Voltage: 16V; Wattage: NA; Weight: 0.33mg; Datasheet: Y:\MIS_DATABASE\DATASHEETS\CAPACITORS\GRM033R61C104KE14.PDF
C508 = CAP: CAP CERAMIC 10uF 10V 20% X5R 0402; Chkd/date: MANIRAJA/300520; Crtd /date: ALVY/260520; Custom_Duty: 15%; Customs_HS_Code: 85322990; Distributor_name: DIGIKEY; Distributor_part_number: 490-GRM155R61A106ME11DTR-ND; Footprint Path: Y:\MIS_DATABASE\Library\ALTIUM_TOOL\PCB_FOOTPRINTS\Altium_Footprint_Lib.PcbLib; Height: 0.55MM; Library Path: Y:\MIS_DATABASE\Library\ALTIUM_TOOL\SCHEMATICS_PARTS\MS_DISCRETE_Library.schlib; Mfr_name: MURATA; Mfr_part_number: GRM155R61A106ME11D; Mistral Part No: 120013110019-R; Package: 0402; Part_type: CAPACITORS\CERAMIC; Project: QCS610_NANOSOM; RoHS: RoHS; Temperature: -55°C+85°C; Tolerance: 20%; Voltage: 10V; Wattage: NA; Weight: 3.1mg; Datasheet: Y:\MIS_DATABASE\DATASHEETS\CAPACITORS\MURATA-GXX-SER_NOV17.PDF
D15 = DIODE_SOD323: DIODE 1CH ESD PROTECTION X1SON2; Chkd/date: MANIRAJA/040420; Crtd /date: VASANTHA/181114; Custom_Duty: 15%; Customs_HS_Code: 85423100; Distributor_name: DIGIKEY; Distributor_part_number: 296-30406-1-ND; Footprint Path: Y:\MIS_DATABASE\Library\ALTIUM_TOOL\PCB_FOOTPRINTS\Altium_Footprint_Lib.PcbLib; Height: 0.45MM; Library Path: Y:\MIS_DATABASE\Library\ALTIUM_TOOL\SCHEMATICS_PARTS\MS_DISCRETE_Library.schlib; Mfr_name: TEXAS INSTRUMENTS; Mistral Part No: 130014110022-R; Package: X1SON2; Part_type: DIODE; Project: GALILEO_EVM; RoHS: RoHS; Temperature: -40°C+125°C; Tolerance: NA; Voltage: NA; Wattage: NA; Weight: 1mg; Datasheet: Y:\MIS_DATABASE\DATASHEETS\ICS\INTERFACE\TPD1E10B06-SER.PDF
L5 L7 L8 = INDUCTOR: IND CHIP 0.47uH 4.5A 20% 0806; Chkd/date: MANIRAJA/121020; Crtd /date: ALVY/121020; Custom_Duty: 24%; Customs_HS_Code: 85437099; Distributor_name: DIGIKEY; Distributor_part_number: DFE201612E-R47M=P2-ND; Footprint Path: Y:\MIS_DATABASE\Library\ALTIUM_TOOL\PCB_FOOTPRINTS\Altium_Footprint_Lib.PcbLib; Height: 1.20MM; Library Path: Y:\MIS_DATABASE\Library\ALTIUM_TOOL\SCHEMATICS_PARTS\MS_DISCRETE_Library.schlib; Mfr_name: MURATA; Mfr_part_number: DFE201612E-R47M=P2; Mistral Part No: 130020100030-R; Package: 0806; Project: AM64X_SKEVM; RoHS: RoHS; Temperature: -40°C+125°C; Tolerance: 20%; Voltage: NA; Wattage: NA; Weight: 18.8mg; Datasheet: Y:\MIS_DATABASE\DATASHEETS\DISCRETES\INDUCTORS\DFE201612E.PDF
R101 R615 = RESISTOR: RES 0E 1/16W JUMPER 0402; Chkd/date: VASANTHA/201216; Crtd /date: MUDDU/190810; Custom_Duty: 15%; Customs_HS_Code: 85332119; Distributor_name: DIGIKEY; Distributor_part_number: 541-0.0JCT-ND; Footprint Path: Y:\MIS_DATABASE\Library\ALTIUM_TOOL\PCB_FOOTPRINTS\Altium_Footprint_Lib.PcbLib; Height: 0.40MM; Library Path: Y:\MIS_DATABASE\Library\ALTIUM_TOOL\SCHEMATICS_PARTS\MS_DISCRETE_Library.schlib; Mfr_name: VISHAY; Mfr_part_number: CRCW04020000Z0ED; Mistral Part No: 110010080019-R; Package: 0402; Part_type: RESISTORS\FIXED; Project: PB_BUGBASE; RoHS: RoHS; Temperature: -55°C+155°C; Tolerance: NA; Voltage: NA; Wattage: 1/16W; Weight: 0.65mg; Datasheet: Y:\MIS_DATABASE\DATASHEETS\RESISTORS\CRCW0603.PDF
R618 R620 R621 R624 R675 R679 R682 = RESISTOR: RES 10K 1/20W 5% 0201; Chkd/date: VASANTHA/061216; Crtd /date: MAZHAR/040505; Custom_Duty: 15%; Customs_HS_Code: 85332119; Distributor_name: DIGIKEY; Distributor_part_number: P10KAGCT-ND; Footprint Path: Y:\MIS_DATABASE\Library\ALTIUM_TOOL\PCB_FOOTPRINTS\Altium_Footprint_Lib.PcbLib; Height: 0.26MM; Library Path: Y:\MIS_DATABASE\Library\ALTIUM_TOOL\SCHEMATICS_PARTS\MS_DISCRETE_Library.schlib; Mfr_name: PANASONIC-ECG; Mfr_part_number: ERJ-1GEJ103C; Mistral Part No: 110010070051-R; Package: 0201; Part_type: RESISTORS\FIXED; Project: G4_SVGA; RoHS: RoHS; Temperature: -55°C+125°C; Tolerance: 5%; Voltage: NA; Wattage: 1/20W; Weight: 0.15mg; Datasheet: Y:\MIS_DATABASE\DATASHEETS\RESISTORS\PAN-ERJXGE-FEB06.PDF
R651 = RESISTOR: RES 1K 1/20W 1% 0201; Chkd/date: PRAVEEN/110822; Crtd /date: PRAVEEN/110822; Custom_Duty: 15%; Customs_HS_Code: 85332119; Distributor_name: DIGIKEY; Distributor_part_number: P122413CT-ND; Footprint Path: Y:\MIS_DATABASE\Library\ALTIUM_TOOL\PCB_FOOTPRINTS\Altium_Footprint_Lib.PcbLib; Height: 0.26MM; Library Path: Y:\MIS_DATABASE\Library\ALTIUM_TOOL\SCHEMATICS_PARTS\MS_DISCRETE_Library.schlib; Manufacturer: YAGEO AMERICA; Mfr_name: PANASONIC-ECG; Mfr_part_number: ERJ-1GNF1001C; Mistral Part No: 110022080039-R; Package: 0201; Part_type: RESISTORS\FIXED; Project: QCS6490 SOM_BRD; RoHS: RoHS; Temperature: -55°C+125°C; Tolerance: 1%; Voltage: NA; Wattage: 1/20W; Weight: 0.15mg; Datasheet: Y:\MIS_DATABASE\DATASHEETS\RESISTORS\PAN-ERJSER_NOV17.PDF
SW5 = SW4_EVQP: SWITCH TACTILE SPST RT SMD; Chkd/date: MANIRAJA/051020; Crtd /date: ALVY/011020; Custom_Duty: 24%; Customs_HS_Code: 85369090; Distributor_name: DIGIKEY; Distributor_part_number: 732-7059-1-ND; Footprint Path: Y:\MIS_DATABASE\Library\ALTIUM_TOOL\PCB_FOOTPRINTS\Altium_Footprint_Lib.PcbLib; Height: 1.65MM; Library Path: Y:\MIS_DATABASE\Library\ALTIUM_TOOL\SCHEMATICS_PARTS\MS_SWITCH_Library.schlib; Mfr_name: WURTH ELECTRONICS; Mistral Part No: 130020100002-R; Package: SMD; Part_type: ELECTRO-MECHANICAL\SWITCH; Project: AM64X_SKEVM; RoHS: RoHS; Temperature: -40°C+85°C; Tolerance: NA; Voltage: NA; Wattage: NA; Weight: 50mg; Datasheet: Y:\MIS_DATABASE\DATASHEETS\MISC\SWITCHES\436331045822.PDF
U14 = TPS65219_QFN32: IC INTEGRATED POWER MANAGEMENT FOR ARM CORTEX-A53 PROCESSOR AND FPGA QFN32; Chkd/date: PRAVEEN/211022; Crtd /date: PRAVEEN/211022; Custom_Duty: 15%; Customs_HS_Code: 85423100; Distributor_name: NA; Distributor_part_number: NA; Footprint Path: Y:\MIS_DATABASE\Library\ALTIUM_TOOL\PCB_FOOTPRINTS\Altium_Footprint_Lib.PcbLib; Height: 1.00MM; Library Path: Y:\MIS_DATABASE\Library\ALTIUM_TOOL\SCHEMATICS_PARTS\MS_MISCPOWER_Library.schlib; Mfr_name: TEXAS INSTRUMENTS; Mistral Part No: 142022100015-R; Package: QFN32; Part_type: ICS\POWER\MANAGEMENT; Project: AM64X_SK; RoHS: NA; Temperature: -40°C+85°C; Tolerance: NA; Voltage: NA; Wattage: NA; Weight: NA; Datasheet: Y:\MIS_DATABASE\DATASHEETS\ICS\POWER\TPS6521904RHBR.PDF
U104 = TPS22965DSGT_WSON8: IC 5.7V 6A 1-CHANNEL 16mE ON-RESISTANCE LOAD SWITCH WSON8; Chkd/date: MANIRAJA/080817; Crtd /date: VASANTHA/280714; Custom_Duty: 15%; Customs_HS_Code: 85423100; Distributor_name: DIGIKEY; Distributor_part_number: 296-34943-1-ND; Footprint Path: Y:\MIS_DATABASE\Library\ALTIUM_TOOL\PCB_FOOTPRINTS\Altium_Footprint_Lib.PcbLib; Height: 0.80MM; Library Path: Y:\MIS_DATABASE\Library\ALTIUM_TOOL\SCHEMATICS_PARTS\MS_MISCPOWER_Library.schlib; Mfr_name: TEXAS INSTRUMENTS; Mistral Part No: 142014070020-R; Package: WSON8; Part_type: ICS\POWER\DRIVER; Project: DC_MIST_DIGITAL CARD; RoHS: RoHS; Temperature: -40°C+105°C; Tolerance: NA; Voltage: NA; Wattage: NA; Weight: 11mg; Datasheet: Y:\MIS_DATABASE\DATASHEETS\ICS\POWER\TPS22965-SER.PDF

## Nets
DGND: C50.2 C52.2 C86.1 C87.2 C92.2 C95.2 C98.2 C100.2 C104.2 C107.2 C108.2 C110.2 C112.2 C117.2 C122.2 C149.2 C154.2 C155.2 C158.2 C160.2 C164.2 C320.2 C357.2 C395.2 C396.2 C400.2 C407.2 C414.2 C418.2 C419.2 C420.2 C424.2 C425.2 C426.2 C494.2 C495.2 C499.1 C502.2 C503.2 C506.1 C507.1 C508.2 D15.1 R104.2 R454.2 R467.2 R643.2 R645.2 SW5.2 SW5.4 TP96.1(TP) TP97.1(TP) TP98.1(TP) TP99.1(TP) U14.15(AGND) U14.33(PGND) U21.2(GND) U21.5(EP) U24.2(GND) U24.5(EP) U67.3(AGND) U67.9(PGND1) U67.11(PGND2) U76.4(GND) U76.10(PGND) U76.15(VSEL) U104.5(GND) U104.9(EP) ; also on sheet 1 10 14 15 16 17 18 19 20 21 22 23 24 25 26 27 28 29 30 31 32 33 34 35 36 37 38 39 40 41 42 43
VCC_1V8: C52.1 C100.1 C117.1 L7.2 R116.1 TP41.1(TP) U14.20(PVIN_LDO2) U14.32(FB_B2) U24.4(IN) ; also on sheet 14 18 19 21 25 34 37 39 40 42
VCC_3V3_FB: C402.2 R455.2 R467.1 U67.4(FB)
VCC_3V3_MAIN: C50.1 C87.1 C104.1 C108.1 C110.1 C154.1 C320.1 C395.1 C419.1 C426.1 C502.1 C506.2 C508.1 L12.2 R453.1 R455.1 R461.1 R618.1 R675.2 R679.1 R682.2 TP51.1(TP) U14.4(PVIN_B1_1) U14.5(PVIN_B1_2) U14.6(PVIN_LDO1) U14.13(VSYS) U14.22(PVIN_LDO34) U14.26(PVIN_B3) U14.30(PVIN_B2) U67.1(BIAS) U104.1(VIN1) U104.2(VIN2) U104.4(VBIAS) ; also on sheet 15 26
VCC_3V3_PG: R453.2 U67.5(PGOOD)
VCC_3V3_SYS: C92.1 C507.2 R620.2 R621.2 R624.2 TP112.1(TP) U21.4(IN) U104.7(VOUT1) U104.8(VOUT2) ; also on sheet 10 14 18 19 20 22 23 24 25 26 27 29 30 31 32 33 34 35 36 37 38 39 40 41 42 43
VCC_5V0: C155.1 C158.1 C160.1 C420.1 R509.2 R646.1 TP70.1(TP) U76.7(VOUT) ; also on sheet 10 33 36 41
VCC_5V0_EN: R676.1 R682.1 TP115.1(TP) U76.14(EN)
VCC_5V0_FB: R645.1 R646.2 U76.5(FB)
VCC_5V0_PG: R509.1 U76.2(PG)
VCC_CORE: C122.1 C495.1 L5.2 TP45.1(TP) U14.1(FB_B1) ; also on sheet 14
VDD_1V0: C95.1 TP33.1(TP) U24.1(OUT) ; also on sheet 23 24
VDD_1V2: C112.1 L8.2 TP40.1(TP) U14.24(FB_B3) ; also on sheet 14 41
VDD_2V5: C357.1 TP42.1(TP) U14.23(VLDO4) ; also on sheet 17 23 24
VDD_LDO2: C107.1 U14.19(VLDO2) ; also on sheet 14
VDDA1V8: C98.1 U14.21(VLDO3) ; also on sheet 14
VDDSHV_SDIO: R101.2 TP29.1(TP) ; also on sheet 15 20
VDDSHV_SDIO_R: C503.1 R101.1 U14.7(VLDO1)
CBOOT: C413.1 U67.13(RBOOT) U67.14(CBOOT)
EXTINTn: R678.1 ; also on sheet 42
LM61460_EN: R680.2 U67.7(EN/SYNC)
LM61460_RT: R454.1 U67.6(RT)
LM61460_SW: C413.2 L12.1 U67.10(SW)
LM61460_VCC: C407.1 U67.2(VCC)
PMIC_INTn: R678.2 U14.11(nINT)
PMIC_PBn: R618.2 R651.2 SW5.1 TP116.1(TP) U14.25(EN/PB/VSENSE)
PMIC_PGOOD: R620.1 TP113.1(TP) U14.18(nRSTOUT) ; also on sheet 35 42
PMIC_SCL: R638.2 TP108.1(TP) U14.10(SCL)
PMIC_SDA: R639.2 TP109.1(TP) U14.9(SDA)
PMIC_STBY: R621.1 TP104.1(TP) U14.31(MODE/STBY)
RESETSTATz: R615.1 ; also on sheet 19 20 21 23 24 27 32 33 37 39 40 41 42
SoC_I2C0_SCL: R638.1 ; also on sheet 10 22 32 33 37 42
SoC_I2C0_SDA: R639.1 ; also on sheet 10 22 32 33 37 42
SW_1V2_DDR: L8.1 U14.27(LX_B3)
SW_VCC_1V8: L7.1 U14.29(LX_B2)
SW_VCC_CORE: L5.1 U14.2(LX_B1_1) U14.3(LX_B1_2)
TEST_POWERDOWN: R651.1 ; also on sheet 1 26
TPS22965_EN: R675.1 R677.1 TP111.1(TP) U104.3(ON)
VMAIN: C149.1 C396.1 C400.1 C414.1 C418.1 C424.1 C425.1 R533.1 R680.1 TP95.1(TP) U67.8(VIN1) U67.12(VIN2) U76.12(VIN) ; also on sheet 10
VPP_1V8: C86.2 TP31.1(TP) U21.1(OUT) ; also on sheet 15
VPP_LDO_EN: R104.1 R105.1 ; also on sheet 39
VSEL_SD_SOC: R624.1 TP105.1(TP) U14.12(VSEL_SD/VSEL_DDR) ; also on sheet 32
N19859568: L13.1 U76.11(L1)
N19859570: L13.2 U76.9(L2)
N19859674: R643.1 U76.6(FB2)
N19859678: R533.2 U76.1(PS/SYNC)
N19859810: C164.1 U76.3(VAUX)
N20239386: C494.1 U14.14(VDD1P8)
N20239533: R676.2 U14.8(GPO1)
N20240161: TP114.1(TP) U14.16(GPIO)
N20240180: R615.2 U14.28(MODE/RESET)
N20240340: R677.2 U14.17(GPO2)
N20240412: C499.2 D15.2 R679.2 SW5.3
N20242777: R105.2 U21.3(EN)
N20243098: C402.1 R461.2
N20243217: R116.2 U24.3(EN)

Not connected (* = marked no-connect by the designer): U104 6(CT)*

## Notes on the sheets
sheet 11
- PERIPHERAL POWER SUPPLIES - 1
- GROUND TEST POINTS
sheet 12
- PERIPHERAL POWER SUPPLIES - 2
- 3.3V, 6.0 AMPS SUPPLY
- VinMin = 4.5V
  VinMax = 24V
  Vout = 3.3V @ 6A
- D-Note:-
  Add a Jumper or OR for isolation
  or Current measurement for
  preproduction board
- CAD Note:- Tie the feedback after the bulk caps
- PERIPHERAL SUPPLY - ETHERNET PHY
- 1.0V, 0.5 AMPS
- 1.8V VPP, 0.5 AMPS SUPPLY
- D-Note :-
  It is very important to select
  an LDO with very fast transient
  response and connect its output
  to the VPP pin with a low loop
  inductance path to ensure it is
  able to source the high
  transient load, where the VPP
  pin never drops below the
  minimum operating voltage.
- D-Note:- Add a series resistor to the VPP
   supply pin for isolation or testing
- D-Note :-
  An alternative way to
  source the VPP is to use
  an external supply. The
  required caps and
  termination/Discharge
  resistor are recommended
  to be placed near to the
  SoC VPP pin.
  SOC GPIO output can be
  used to control or time
  the external power supply
  output
- CAD Note:- Move
  pulldown near to
  EN pin - pin 3
  of LDO
- D-Note:- Add an
  additional  decap
  0.1 uF near to the
  SoC VPP pin
- D-Note :-
  Alternate part suggestion
  TPS7A21-Q1, Automotive, 500mA, low-noise ultra-low-IQ
  high-PSRR low-dropout (LDO) voltage regulator
- D-Note :-
  Given the transient current requirement during eFuse programming, using
  load switch or FET switch may not be a recommended approach,
  It is recommended to use an LDO.  A load or FET switch is likely to have
  too much voltage drop that can't be compensated like when using an LDO.
sheet 13
- SOC POWER SUPPLY PMIC
         TPS6521904 PMIC
- D-Note :-
  Verify the PMIC data sheet for the recommended caps
  for the DC/DC and LDO outputs and  provide the
  recommended caps
- D-Note :-
  Show the bulk caps connection  for each of the
  DC/DC inputs separately
  Add a 0.1 uF across the bulk caps
  PVIN_B1_1, PVIN_B1_2 can share the same bulk cap
- Input Caps for pin 4,5,26,30
- D-Note
  Add a 0R resistor or Jumper at the output of
  the DC/DC  for isolation or testing
- R-Note :-
  Refer PMIC data sheet and
  schematics review checklist
  for reviewing the
  implementation of PMIC section
- PMIC REGULATORS
- VOLTAGE RAIL
- CURRENT(mA)
- BUCK 1
- VCC_CORE(0.85V)
- 2700
- SILK SCREEN :
  TP45 - VCC_CORE (configured to 0.85V)
  TP41 - VCC_1V8
  TP40 - VDD_1V2
  TP29 - VDDSHV_SDIO
  TP42 - VDD_2V5
- BUCK 2
- VCC_1V8
- 995
- BUCK 3
- VDD_1V2
- 936
- LDO 1
- VDDSHV_SDIO
- 50
- LDO 2
- VDD_LDO2
- 150
- Devices Powered :
  HDMI interface
  DDR
- LDO 3
- VDDA1V8
- 200
- LDO 4
- VDD_2V5
- 300
- Devices Powered :
  Ethernet PHY
  DDR
- R-Note
  SD card interface IO supply voltage switching (3.3V/1.8V)
  is required to support higher speed data rates
  Refer SOC data sheet for supported rates and IO voltage
  levels
- Configured as PB(Active Low)
- CAD Note:- Tie the feedback after the DC/DC output bulk caps
- I2C ADDRESS: 0x30
- SOC 3.3V IO SUPPLY
- VCC_3V3_SYS LOAD SWITCH
- PMIC ON/OFF PUSH BUTTON LOGIC
- D- Note:- Add a cap (220 pF  or Higher) to
  the CT pin for SoC IO supply slew rate
  control.
  SoC IO supplies have slew rate requirements
  specified
